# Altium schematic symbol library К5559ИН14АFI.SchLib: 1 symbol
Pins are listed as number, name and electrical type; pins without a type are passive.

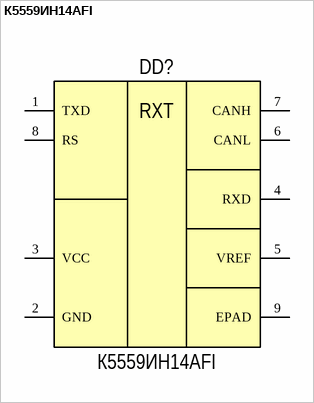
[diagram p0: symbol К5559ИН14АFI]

## К5559ИН14АFI
designator DD?  Part Number: К5559ИН14АFI
FullName: Микросхема К5559ИН14АFI ТСКЯ.431000.003ТУ, ТСКЯ.431323.049СП; Поставщик: Миландр
footprint К5559ИН14АFI (DFN8 5x6x0,75 (1,27))
pins: 1 TXD, 2 GND, 3 VCC, 4 RXD, 5 VREF, 6 CANL, 7 CANH, 8 RS, 9 EPAD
